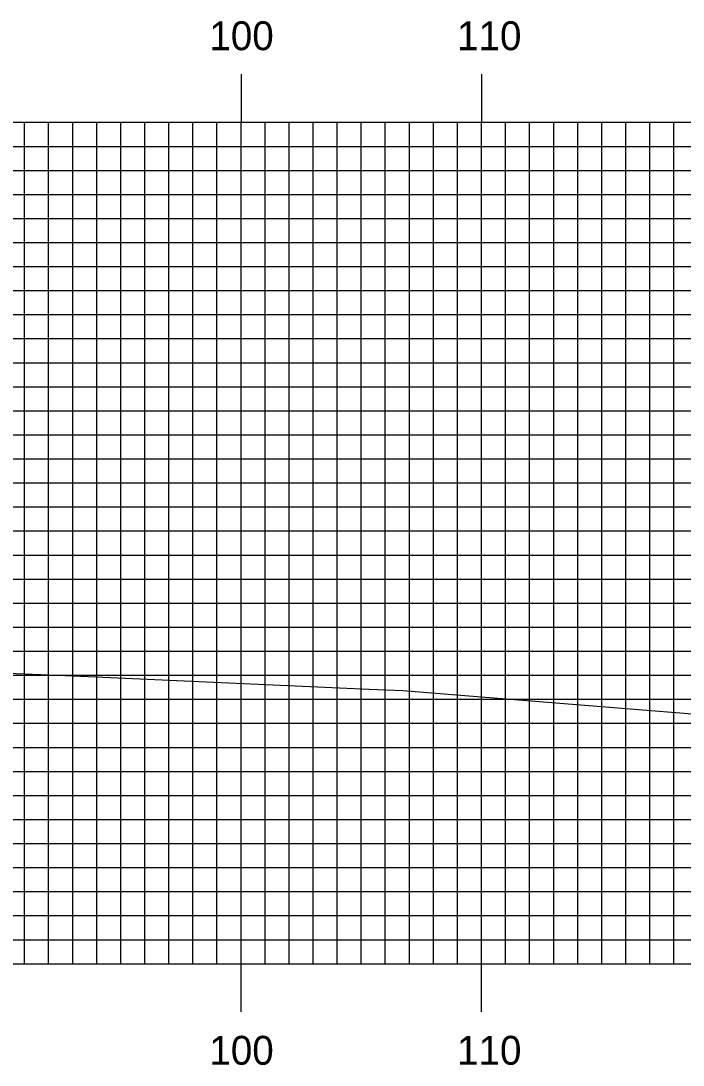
# Model space of a CAD drawing. Extents: x 1807045 to 1807388, y 442591 to 442811.
# Drawn here: x 1807301.61 to 1807329.14, y 442659.45 to 442702.88 of the extents above; entities that cross this region are included whole.
import ezdxf

# ---------------------------------------------------------------- set-up
doc = ezdxf.new("R2010")
doc.units = 0
for name, color, linetype in [('H_V ANNOTATION', 7, 'Continuous'), ('MAJOR', 7, 'Continuous'), ('MINOR', 7, 'Continuous'), ('S_Roadway_Centerline', 7, 'Continuous')]:
    doc.layers.add(name, color=color, linetype=linetype)

msp = doc.modelspace()

# ---------------------------------------------------------------- linework, layer by layer
at = {"layer": 'MAJOR'}
for p, q in [((1807310.759, 442700.669), (1807310.759, 442698.665)), ((1807320.759, 442700.669), (1807320.759, 442698.665)), ((1807070.759, 442698.665), (1807350.759, 442698.665)), ((1807070.759, 442698.665), (1807350.759, 442698.665)), ((1807310.759, 442663.665), (1807310.759, 442698.665)), ((1807320.759, 442663.665), (1807320.759, 442698.665)), ((1807070.759, 442693.665), (1807350.759, 442693.665)), ((1807070.759, 442688.665), (1807350.759, 442688.665)), ((1807070.759, 442683.665), (1807350.759, 442683.665)), ((1807070.759, 442678.665), (1807350.759, 442678.665)), ((1807070.759, 442673.665), (1807350.759, 442673.665)), ((1807070.759, 442668.665), (1807350.759, 442668.665)), ((1807070.759, 442663.665), (1807350.759, 442663.665)), ((1807070.759, 442663.665), (1807350.759, 442663.665)), ((1807310.759, 442661.661), (1807310.759, 442663.665)), ((1807320.759, 442661.661), (1807320.759, 442663.665))]:
    msp.add_line(p, q, dxfattribs=at)
at = {"layer": 'MINOR'}
for p, q in [((1807301.759, 442663.665), (1807301.759, 442698.665)), ((1807302.759, 442663.665), (1807302.759, 442698.665)), ((1807303.759, 442663.665), (1807303.759, 442698.665)), ((1807304.759, 442663.665), (1807304.759, 442698.665)), ((1807305.759, 442663.665), (1807305.759, 442698.665)), ((1807306.759, 442663.665), (1807306.759, 442698.665)), ((1807307.759, 442663.665), (1807307.759, 442698.665)), ((1807308.759, 442663.665), (1807308.759, 442698.665)), ((1807309.759, 442663.665), (1807309.759, 442698.665)), ((1807311.759, 442663.665), (1807311.759, 442698.665)), ((1807312.759, 442663.665), (1807312.759, 442698.665)), ((1807313.759, 442663.665), (1807313.759, 442698.665)), ((1807314.759, 442663.665), (1807314.759, 442698.665)), ((1807315.759, 442663.665), (1807315.759, 442698.665)), ((1807316.759, 442663.665), (1807316.759, 442698.665)), ((1807317.759, 442663.665), (1807317.759, 442698.665)), ((1807318.759, 442663.665), (1807318.759, 442698.665)), ((1807319.759, 442663.665), (1807319.759, 442698.665)), ((1807321.759, 442663.665), (1807321.759, 442698.665)), ((1807322.759, 442663.665), (1807322.759, 442698.665)), ((1807323.759, 442663.665), (1807323.759, 442698.665)), ((1807324.759, 442663.665), (1807324.759, 442698.665)), ((1807325.759, 442663.665), (1807325.759, 442698.665)), ((1807326.759, 442663.665), (1807326.759, 442698.665)), ((1807327.759, 442663.665), (1807327.759, 442698.665)), ((1807328.759, 442663.665), (1807328.759, 442698.665)), ((1807070.759, 442697.665), (1807350.759, 442697.665)), ((1807070.759, 442696.665), (1807350.759, 442696.665)), ((1807070.759, 442695.665), (1807350.759, 442695.665)), ((1807070.759, 442694.665), (1807350.759, 442694.665)), ((1807070.759, 442692.665), (1807350.759, 442692.665)), ((1807070.759, 442691.665), (1807350.759, 442691.665)), ((1807070.759, 442690.665), (1807350.759, 442690.665)), ((1807070.759, 442689.665), (1807350.759, 442689.665)), ((1807070.759, 442687.665), (1807350.759, 442687.665)), ((1807070.759, 442686.665), (1807350.759, 442686.665)), ((1807070.759, 442685.665), (1807350.759, 442685.665)), ((1807070.759, 442684.665), (1807350.759, 442684.665)), ((1807070.759, 442682.665), (1807350.759, 442682.665)), ((1807070.759, 442681.665), (1807350.759, 442681.665)), ((1807070.759, 442680.665), (1807350.759, 442680.665)), ((1807070.759, 442679.665), (1807350.759, 442679.665)), ((1807070.759, 442677.665), (1807350.759, 442677.665)), ((1807070.759, 442676.665), (1807350.759, 442676.665)), ((1807070.759, 442675.665), (1807350.759, 442675.665)), ((1807070.759, 442674.665), (1807350.759, 442674.665)), ((1807070.759, 442672.665), (1807350.759, 442672.665)), ((1807070.759, 442671.665), (1807350.759, 442671.665)), ((1807070.759, 442670.665), (1807350.759, 442670.665)), ((1807070.759, 442669.665), (1807350.759, 442669.665)), ((1807070.759, 442667.665), (1807350.759, 442667.665)), ((1807070.759, 442666.665), (1807350.759, 442666.665)), ((1807070.759, 442665.665), (1807350.759, 442665.665)), ((1807070.759, 442664.665), (1807350.759, 442664.665))]:
    msp.add_line(p, q, dxfattribs=at)
at = {"layer": 'S_Roadway_Centerline'}
msp.add_lwpolyline([(1807259.938, 442676.383), (1807289.258, 442676.117), (1807292.175, 442676.101), (1807293.147, 442676.082), (1807293.932, 442676.046), (1807303.798, 442675.634), (1807316.087, 442675.089), (1807317.483, 442675.029), (1807339.15, 442673.287), (1807345.472, 442673.075), (1807349.323, 442673.138), (1807350.759, 442673.094)], dxfattribs=at)

# ---------------------------------------------------------------- texts
at = {"layer": 'H_V ANNOTATION'}
for s, p in [('100', (1807309.442, 442701.665)), ('110', (1807319.742, 442701.665)), ('100', (1807309.442, 442659.465)), ('110', (1807319.742, 442659.465))]:
    msp.add_text(s, height=1.2, dxfattribs=at).set_placement(p)

doc.saveas('drawing.dxf')
